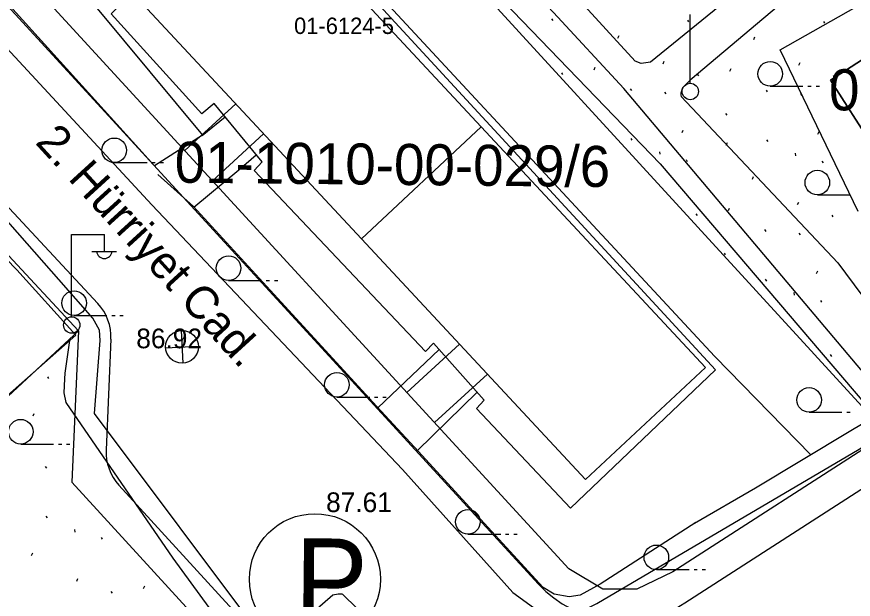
# Model space of a CAD drawing. Extents: x 412225 to 413380, y 4456471 to 4457189.
# Drawn here: x 412564.7 to 412615.8, y 4456958.1 to 4456993.7 of the extents above; entities that cross this region are included whole.
import ezdxf

# ---------------------------------------------------------------- set-up
doc = ezdxf.new("R2010")
doc.units = 0
for name, color, linetype in [('0_HALİHAZIR', 7, 'Continuous'), ('0_KADASTRO', 7, 'Continuous'), ('Level 27', 7, 'Continuous'), ('Level 41', 7, 'Continuous'), ('Level 48', 7, 'Continuous'), ('Level 56', 7, 'Continuous'), ('Level 57', 7, 'Continuous'), ('Level 59', 7, 'Continuous'), ('Level 62', 7, 'Continuous')]:
    doc.layers.add(name, color=color, linetype=linetype)

msp = doc.modelspace()

# ---------------------------------------------------------------- linework, layer by layer
at = {"layer": '0_HALİHAZIR'}
for p, q in [((412605.842, 4456989.61), (412605.842, 4456993.803)), ((412610.722, 4456989.434), (412612.722, 4456989.434)), ((412613.022, 4456989.434), (412613.222, 4456989.434)), ((412613.522, 4456989.434), (412613.722, 4456989.434)), ((412570.687, 4456984.771), (412572.687, 4456984.771)), ((412572.987, 4456984.771), (412573.187, 4456984.771)), ((412573.487, 4456984.771), (412573.687, 4456984.771)), ((412613.599, 4456982.804), (412615.599, 4456982.804)), ((412568.08, 4456975.393), (412568.08, 4456980.394)), ((412568.08, 4456980.394), (412570.08, 4456980.394)), ((412570.08, 4456979.394), (412570.08, 4456980.394)), ((412569.32, 4456979.354), (412570.82, 4456979.354)), ((412577.662, 4456977.584), (412579.662, 4456977.584)), ((412579.962, 4456977.584), (412580.162, 4456977.584)), ((412580.462, 4456977.584), (412580.662, 4456977.584)), ((412568.232, 4456975.457), (412570.232, 4456975.457)), ((412570.532, 4456975.457), (412570.732, 4456975.457)), ((412571.032, 4456975.457), (412571.232, 4456975.457)), ((412574.891, 4456972.532), (412574.785, 4456974.529)), ((412573.82, 4456973.467), (412575.817, 4456973.572)), ((412584.275, 4456970.476), (412586.275, 4456970.476)), ((412586.575, 4456970.476), (412586.775, 4456970.476)), ((412587.075, 4456970.476), (412587.275, 4456970.476)), ((412613.098, 4456969.55), (412615.098, 4456969.55)), ((412615.398, 4456969.55), (412615.598, 4456969.55)), ((412564.977, 4456967.611), (412566.977, 4456967.611)), ((412567.277, 4456967.611), (412567.477, 4456967.611)), ((412567.777, 4456967.611), (412567.977, 4456967.611)), ((412592.272, 4456962.114), (412594.272, 4456962.114)), ((412594.572, 4456962.114), (412594.772, 4456962.114)), ((412595.072, 4456962.114), (412595.272, 4456962.114)), ((412603.774, 4456959.948), (412605.774, 4456959.948)), ((412606.074, 4456959.948), (412606.274, 4456959.948)), ((412606.574, 4456959.948), (412606.774, 4456959.948))]:
    msp.add_line(p, q, dxfattribs=at)
for points in [[(412550.421, 4457048.668), (412537.602, 4457036.715), (412532.744, 4457031.597), (412531.645, 4457030.352), (412531.215, 4457029.661), (412531.098, 4457028.843), (412531.362, 4457028.03), (412531.543, 4457027.725), (412531.832, 4457027.378), (412543.375, 4457013.781), (412559.043, 4456997.247), (412572.981, 4456982.195), (412588.276, 4456966.063), (412595.013, 4456958.555)], [(412618.011, 4456970.089), (412601.784, 4456989.285), (412597.499, 4456993.919), (412584.651, 4457007.493), (412572.447, 4457021.034), (412559.645, 4457035.007), (412549.011, 4457046.675)], [(412607.96, 4456994.581), (412603.406, 4456990.9), (412602.853, 4456990.808), (412602.472, 4456990.962), (412588.105, 4457006.674), (412591.674, 4457010.37), (412596.48, 4457010.067), (412596.517, 4457009.396), (412598.763, 4457009.265), (412598.644, 4457010.245), (412606.63, 4457010.201), (412609.679, 4457007.288), (412609.056, 4457006.565), (412610.658, 4457004.849), (412611.379, 4457005.602), (412615.519, 4457001.438), (412615.561, 4457001.083), (412615.452, 4457000.87), (412614.868, 4457000.182)], [(412649.642, 4456989.118), (412640.963, 4456999.318), (412630.88, 4457010.14), (412630.62, 4457010.288), (412630.4, 4457010.275), (412630.103, 4457010.181), (412616.891, 4456999.117), (412605.829, 4456989.802), (412605.366, 4456989.327), (412605.264, 4456989.016), (412605.258, 4456988.894), (412605.278, 4456988.808), (412614.848, 4456978.658), (412620.293, 4456971.32)], [(412580.997, 4457008.535), (412604.005, 4456984.694), (412617.154, 4456969.318)], [(412616.09, 4456981.796), (412611.338, 4456991.643), (412634.987, 4457005.042), (412639.214, 4456997.464), (412645.21, 4456986.569)], [(412573.146, 4456984.576), (412563.344, 4456995.419), (412555.714, 4457004.03)], [(412613.201, 4456966.944), (412607.333, 4456972.952), (412579.486, 4457002.942), (412569.647, 4456994.171), (412576.069, 4456986.441), (412573.146, 4456984.576)], [(412553.419, 4456989.855), (412564.734, 4456978.225), (412568.348, 4456974.246), (412544.691, 4456953.408), (412533.004, 4456941.924), (412518.623, 4456957.688), (412515.821, 4456960.985)], [(412576.061, 4456986.435), (412577.447, 4456987.557)], [(412575.546, 4456982.062), (412578.296, 4456984.34), (412579.356, 4456985.252)], [(412584.762, 4456948.165), (412585.534, 4456948.579), (412586.037, 4456949.02), (412586.337, 4456949.57), (412586.364, 4456950.073), (412586.006, 4456950.99), (412584.455, 4456952.83), (412587.206, 4456955.305), (412587.296, 4456955.619), (412587.226, 4456955.918), (412584.641, 4456958.441), (412584.604, 4456958.443), (412584.347, 4456958.456), (412584.036, 4456958.399), (412581.664, 4456956.335), (412580.856, 4456955.468), (412580.642, 4456955.381), (412579.867, 4456955.606), (412569.482, 4456969.462), (412569.816, 4456973.933), (412569.776, 4456974.563), (412569.384, 4456975.285), (412561.794, 4456983.876)], [(412575.523, 4456982.088), (412573.339, 4456984.042)], [(412586.714, 4456969.892), (412575.523, 4456982.088)], [(412595.013, 4456958.555), (412596.492, 4456957.475), (412597.153, 4456957.238), (412597.959, 4456957.201), (412599.237, 4456957.433), (412600.135, 4456957.874), (412616.154, 4456967.297), (412638.119, 4456980.873)], [(412513.106, 4456909.948), (412516.87, 4456911.126), (412523.559, 4456914.13), (412540.165, 4456923.952), (412557.772, 4456934.57), (412570.175, 4456941.896), (412581.984, 4456949.168), (412582.162, 4456949.515), (412582.19, 4456949.809), (412574.277, 4456960.644), (412567.756, 4456970.138), (412567.627, 4456970.723), (412567.661, 4456971.595), (412567.679, 4456971.926), (412567.978, 4456973.92)], [(412586.78, 4456969.82), (412590.51, 4456973.382)], [(412589.198, 4456967.206), (412592.835, 4456970.777)], [(412589.249, 4456967.151), (412586.714, 4456969.892)], [(412617.154, 4456969.318), (412615.535, 4456968.346)], [(412615.535, 4456968.346), (412609.83, 4456964.92)], [(412606.188, 4456962.823), (412600.34, 4456959.065), (412599.123, 4456958.386), (412598.448, 4456958.288), (412597.543, 4456958.458), (412596.858, 4456958.859), (412589.225, 4456967.178)], [(412609.83, 4456964.92), (412606.106, 4456962.77)]]:
    msp.add_lwpolyline(points, dxfattribs=at)
msp.add_lwpolyline([(412579.396, 4457002.49), (412607.393, 4456972.127), (412598.534, 4456963.707), (412592.79, 4456969.77), (412593.268, 4456970.292), (412590.176, 4456973.756), (412589.686, 4456973.246), (412579.226, 4456984.295), (412579.716, 4456984.817), (412576.775, 4456988.37), (412576.023, 4456987.752), (412570.488, 4456993.841)], close=True, dxfattribs=at)
for centre, radius in [((412610.722, 4456990.184), 0.75), ((412605.842, 4456989.11), 0.5), ((412570.687, 4456985.521), 0.75), ((412613.599, 4456983.554), 0.75), ((412577.662, 4456978.334), 0.75), ((412568.232, 4456976.207), 0.75), ((412568.09, 4456974.869), 0.5), ((412574.823, 4456973.538), 1), ((412584.275, 4456971.226), 0.75), ((412613.098, 4456970.3), 0.75), ((412564.977, 4456968.361), 0.75), ((412592.272, 4456962.864), 0.75), ((412603.774, 4456960.698), 0.75)]:
    msp.add_circle(centre, radius, dxfattribs=at)
msp.add_arc((412570.08, 4456979.397), 0.474, 184.8384, 355.1464, dxfattribs=at)
at = {"layer": '0_KADASTRO'}
for points in [[(412616.989, 4456969.185), (412581.164, 4457008.273), (412579.783, 4457009.779), (412547.291, 4457045.231), (412547.562, 4457045.484), (412551.915, 4457049.53), (412554.173, 4457051.631), (412567.235, 4457037.411), (412567.703, 4457036.901), (412582.523, 4457050.683), (412586.743, 4457054.608), (412573.215, 4457069.339), (412569.73, 4457073.134), (412570.429, 4457073.754), (412576.154, 4457078.845), (412576.633, 4457078.314), (412593.199, 4457059.967), (412610.332, 4457040.992), (412625.104, 4457054.128)], [(412635.647, 4457003.52), (412614.398, 4456989.798), (412624.745, 4456973.707)], [(412514.918, 4456961.632), (412519.687, 4456956.508), (412533.306, 4456941.862), (412568.504, 4456974.51), (412568.099, 4456965.274), (412587.973, 4456943.566), (412531.386, 4456906.626)]]:
    msp.add_lwpolyline(points, dxfattribs=at)
for points in [[(412565.155, 4456996.219), (412579.783, 4457009.779), (412581.164, 4457008.273), (412616.989, 4456969.185), (412617.864, 4456968.23), (412604.785, 4456959.819), (412602.573, 4456958.764), (412600.503, 4456958.758), (412598.437, 4456960.001), (412566.106, 4456995.183)], [(412614.398, 4456989.798), (412635.647, 4457003.52), (412636.24, 4457003.902), (412647.057, 4456987.08), (412625.215, 4456972.976), (412624.745, 4456973.707)], [(412519.687, 4456956.508), (412554.879, 4456989.15), (412568.504, 4456974.51), (412533.306, 4456941.862)]]:
    msp.add_lwpolyline(points, close=True, dxfattribs=at)
at = {"layer": 'Level 27'}
for points in [[(412592.561, 4457090.519), (412625.322, 4457054.321), (412632.032, 4457046.907), (412649.43, 4457027.697), (412649.43, 4457027.697), (412668.449, 4457006.699), (412669.615, 4457004.71), (412669.079, 4457002.597), (412668.196, 4457000.596), (412654.558, 4456991.925), (412647.057, 4456987.08), (412625.215, 4456972.976), (412617.864, 4456968.23), (412604.785, 4456959.819), (412602.573, 4456958.764), (412600.503, 4456958.758), (412598.437, 4456960.001), (412566.106, 4456995.183), (412565.155, 4456996.219), (412533.021, 4457031.187), (412532.637, 4457031.604)], [(412554.879, 4456989.15), (412568.504, 4456974.51), (412568.099, 4456965.274), (412587.973, 4456943.566)]]:
    msp.add_lwpolyline(points, dxfattribs=at)
at = {"layer": 'Level 41'}
for p, q in [((412597.382, 4456993.547), (412597.451, 4456993.439)), ((412605.675, 4456993.462), (412605.744, 4456993.354)), ((412613.967, 4456993.377), (412614.036, 4456993.27)), ((412601.426, 4456992.362), (412601.5, 4456992.521)), ((412609.719, 4456992.277), (412609.793, 4456992.436)), ((412599.969, 4456990.438), (412600.041, 4456990.598)), ((412604.183, 4456990.803), (412604.254, 4456990.963)), ((412608.261, 4456990.354), (412608.334, 4456990.513)), ((412612.475, 4456990.718), (412612.547, 4456990.878)), ((412597.979, 4456990.251), (412598.049, 4456990.144)), ((412606.271, 4456990.166), (412606.341, 4456990.059)), ((412614.564, 4456990.081), (412614.634, 4456989.974)), ((412602.177, 4456989.279), (412602.247, 4456989.171)), ((412604.274, 4456989.065), (412604.344, 4456988.958)), ((412610.469, 4456989.194), (412610.539, 4456989.086)), ((412612.566, 4456988.98), (412612.636, 4456988.873)), ((412607.999, 4456987.766), (412608.069, 4456987.658)), ((412605.346, 4456986.6), (412605.418, 4456986.758)), ((412613.638, 4456986.515), (412613.711, 4456986.674)), ((412602.213, 4456986.248), (412602.283, 4456986.141)), ((412608.037, 4456985.844), (412608.111, 4456986.003)), ((412610.505, 4456986.163), (412610.575, 4456986.056)), ((412603.963, 4456985.439), (412603.979, 4456985.279)), ((412612.255, 4456985.354), (412612.272, 4456985.194)), ((412605.588, 4456984.953), (412605.657, 4456984.845)), ((412613.88, 4456984.868), (412613.949, 4456984.76)), ((412609.632, 4456983.767), (412609.705, 4456983.926)), ((412612.388, 4456982.209), (412612.46, 4456982.368)), ((412608.174, 4456981.844), (412608.247, 4456982.003)), ((412606.184, 4456981.656), (412606.254, 4456981.55)), ((412614.477, 4456981.571), (412614.547, 4456981.465)), ((412610.382, 4456980.684), (412610.452, 4456980.577)), ((412612.479, 4456980.471), (412612.549, 4456980.363)), ((412607.912, 4456979.257), (412607.982, 4456979.149)), ((412613.551, 4456978.006), (412613.624, 4456978.164)), ((412610.418, 4456977.654), (412610.488, 4456977.546)), ((412612.168, 4456976.845), (412612.185, 4456976.685)), ((412613.793, 4456976.358), (412613.862, 4456976.251)), ((412614.39, 4456973.062), (412614.459, 4456972.955)), ((412566.601, 4456971.717), (412566.671, 4456971.609)), ((412565.727, 4456969.321), (412565.801, 4456969.48)), ((412566.478, 4456966.238), (412566.547, 4456966.13)), ((412569.646, 4456963.559), (412569.654, 4456963.576)), ((412566.514, 4456963.207), (412566.583, 4456963.099)), ((412568.263, 4456962.398), (412568.28, 4456962.238)), ((412569.888, 4456961.912), (412569.957, 4456961.804)), ((412565.64, 4456960.811), (412565.714, 4456960.97)), ((412568.396, 4456959.253), (412568.468, 4456959.412)), ((412572.475, 4456958.803), (412572.547, 4456958.962)), ((412570.485, 4456958.615), (412570.555, 4456958.509))]:
    msp.add_line(p, q, dxfattribs=at)
at = {"layer": 'Level 48'}
msp.add_circle((412582.932, 4456959.36), 4, dxfattribs=at)
at = {"layer": 'Level 57'}
for points in [[(412547.291, 4457045.231), (412579.783, 4457009.779), (412581.164, 4457008.273), (412616.989, 4456969.185), (412617.864, 4456968.23)], [(412625.215, 4456972.976), (412624.745, 4456973.707), (412614.398, 4456989.798), (412635.647, 4457003.52), (412636.24, 4457003.902), (412647.057, 4456987.08)], [(412568.504, 4456974.51), (412533.306, 4456941.862), (412519.687, 4456956.508)]]:
    msp.add_lwpolyline(points, dxfattribs=at)
at = {"layer": 'Level 59'}
for p, q in [((412578.101, 4456988.36), (412574.997, 4456985.508)), ((412585.768, 4456980.123), (412593.089, 4456986.956)), ((412579.804, 4456986.53), (412576.688, 4456983.667)), ((412591.753, 4456973.702), (412588.55, 4456970.759)), ((412593.457, 4456971.874), (412590.242, 4456968.919))]:
    msp.add_line(p, q, dxfattribs=at)
msp.add_lwpolyline([(412572.137, 4456994.767), (412579.458, 4457001.6), (412593.089, 4456986.956), (412606.763, 4456972.286), (412599.442, 4456965.453), (412585.768, 4456980.123)], close=True, dxfattribs=at)
at = {"layer": 'Level 62'}
for points in [[(412596.581, 4456959.065), (412564.633, 4456993.83), (412563.682, 4456994.866), (412529.274, 4457032.309)], [(412667.934, 4456998.06), (412655.637, 4456990.241), (412648.142, 4456985.4), (412626.3, 4456971.296), (412618.947, 4456966.549), (412605.521, 4456957.914)], [(412551.574, 4456995.638), (412569.683, 4456976.179)], [(412570.484, 4456974.004), (412570.187, 4456967.255)], [(412570.972, 4456965.098), (412588.57, 4456945.876)]]:
    msp.add_lwpolyline(points, dxfattribs=at)
for centre, radius, start, end in [((412567.487, 4456974.135), 3, 357.4906, 42.9433), ((412573.185, 4456967.123), 3, 177.4861, 222.4728), ((412601.735, 4456963.802), 7, 222.5825, 302.7455)]:
    msp.add_arc(centre, radius, start, end, dxfattribs=at)

# ---------------------------------------------------------------- texts
at = {"layer": '0_HALİHAZIR'}
msp.add_text('2. Hürriyet Cad.', height=2, rotation=312.3543, dxfattribs=at).set_placement((412565.811, 4456985.976))
for s, p in [('86.92', (412572.028, 4456973.45)), ('87.61', (412583.615, 4456963.459))]:
    msp.add_text(s, height=1.2, dxfattribs=at).set_placement(p)
at = {"layer": '0_KADASTRO'}
msp.add_text('01-6124-5', height=1, dxfattribs=at).set_placement((412581.661, 4456992.616))
msp.add_text('01-6124-5', height=1, dxfattribs=at).set_placement((412581.661, 4456992.616))
at = {"layer": 'Level 48'}
msp.add_text('P', height=5, rotation=359.4141, dxfattribs=at).set_placement((412581.671, 4456956.871))
at = {"layer": 'Level 56'}
for s, p in [('01-1010-00-029/5', (412614.3, 4456987.97)), ('01-1010-00-029/6', (412574.365, 4456983.553))]:
    msp.add_text(s, height=2.5, rotation=359.4136, dxfattribs=at).set_placement(p)

doc.saveas('drawing.dxf')
